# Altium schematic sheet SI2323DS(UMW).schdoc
size 127 x 101 mm
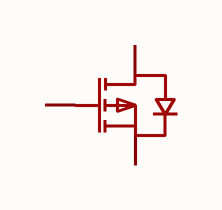
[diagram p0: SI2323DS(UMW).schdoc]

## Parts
Q?  si2323ds(umw)  [SOT-23-3_L2.9-W1.3-P0.95-LS2.4-BR]  (value not drawn)

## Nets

Not connected (* = marked no-connect by the designer): Q? 1(G) 2(S) 3(D)

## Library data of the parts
Q? = si2323ds(umw): 数量:1个P沟道;漏源电压(Vdss):30V;连续漏极电流(Id):4.2A;导通电阻(RDS(on)):50mΩ@10V；65mΩ@4.5V;耗散功率(Pd):1.4W;阈值电压(Vgs(th)):400mV;; Manufacturer: UMW(友台半导体); AddInBom: yes; ModelId: c62791f0466c4ae2a892c056b845b0ca; ModelName: SOT-23-3P_L2.9-W1.3-H1.0-LS2.4-P0.95; ModelTransform: 98.425,114.173,0,180,0,0,0.0005,-0.0005,0; Number: 1个P沟道; Drain to Source Voltage: 30V; Current - Continuous Drain(Id): 4.2A; Pd - Power Dissipation: 1.4W; Gate Threshold Voltage (Vgs(th)): 400mV; Gate Charge(Qg): 9.4nC@4.5V; Input Capacitance(Ciss): 954pF; Reverse Transfer Capacitance (Crss@Vds): 77pF; Output Capacitance(Coss): 115pF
